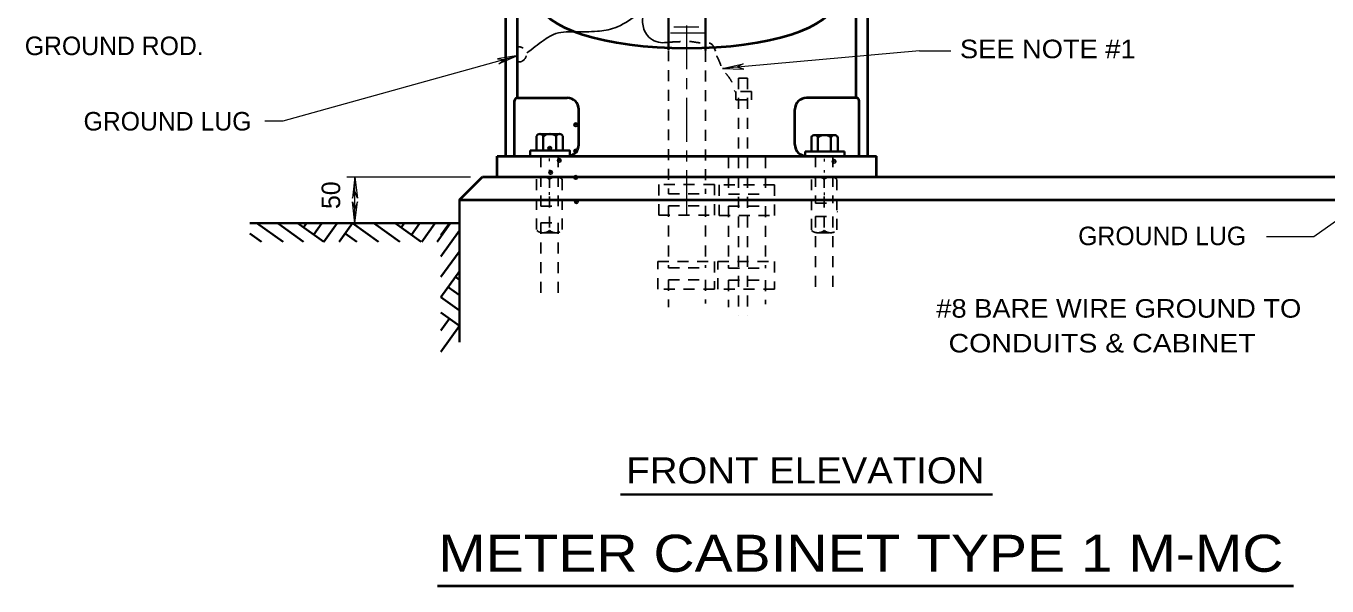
# Model space of a CAD drawing. Extents: x 312583 to 312854, y 144419 to 144597.
# Drawn here: x 312727.8 to 312781.2, y 144519.1 to 144542 of the extents above; entities that cross this region are included whole.
import ezdxf
from ezdxf.enums import TextEntityAlignment as Align

# ---------------------------------------------------------------- set-up
doc = ezdxf.new("R2010")
doc.units = 0
doc.header["$LTSCALE"] = 0.3
doc.header["$PDMODE"] = 32
doc.header["$PDSIZE"] = 0.15
for name, pattern in [('DOTTED', [1.5, 0.3, -1.2]), ('LONG_DASH_SHORT_DASH', [9.9, 6, -1.2, 1.5, -1.2]), ('SHORT_DASHED', [2.7, 1.5, -1.2])]:
    doc.linetypes.add(name, pattern=pattern)
doc.layers.add('1', color=7, linetype='Continuous', lineweight=25)
doc.layers.add('2', color=7, linetype='Continuous', lineweight=13)

msp = doc.modelspace()

# ---------------------------------------------------------------- linework, layer by layer
at = {"layer": '1', "lineweight": 40}
for p, q in [((312747.5013, 144536.686), (312747.5013, 144574.176)), ((312747.9843, 144539.078), (312747.9843, 144574.0686)), ((312761.8763, 144539.078), (312761.8763, 144547.0206)), ((312762.3593, 144536.686), (312762.3593, 144547.0206)), ((312747.8616, 144536.686), (312747.8616, 144538.963)), ((312747.9843, 144539.078), (312750.0159, 144539.078)), ((312761.8763, 144539.078), (312759.8369, 144539.078)), ((312761.9989, 144536.686), (312761.9989, 144538.963)), ((312750.4989, 144537.1613), (312750.4989, 144538.6026)), ((312759.3616, 144537.1613), (312759.3616, 144538.6026)), ((312747.1409, 144536.686), (312762.7119, 144536.686)), ((312747.1409, 144535.8426), (312747.1409, 144536.686)), ((312762.7119, 144535.8426), (312762.7119, 144536.686)), ((312745.6076, 144534.8996), (312746.5429, 144535.835)), ((312746.5429, 144535.835), (312818.4946, 144535.835)), ((312747.1409, 144535.8426), (312762.7119, 144535.8426)), ((312749.0346, 144535.835), (312749.5559, 144535.835)), ((312760.3046, 144535.835), (312760.8259, 144535.835)), ((312745.6076, 144534.8996), (312811.4873, 144534.8996)), ((312779.1799, 144534.8996), (312810.7283, 144534.8996))]:
    msp.add_line(p, q, dxfattribs=at)
at = {"layer": '1', "linetype": 'LONG_DASH_SHORT_DASH', "lineweight": 13}
msp.add_line((312754.9303, 144534.3093), (312754.9303, 144546.2156), dxfattribs=at)
at = {"layer": '1', "lineweight": 35}
for p, q in [((312754.1713, 144542.758), (312754.1713, 144541.0406)), ((312755.6893, 144542.758), (312755.6893, 144541.0176)), ((312748.7663, 144537.5063), (312748.7663, 144536.916)), ((312748.8966, 144537.5906), (312749.7016, 144537.5906)), ((312749.0346, 144537.5063), (312749.0346, 144536.916)), ((312749.5713, 144537.5063), (312749.5713, 144536.916)), ((312749.8396, 144537.5063), (312749.8396, 144536.916)), ((312760.0363, 144537.468), (312760.0363, 144536.8776)), ((312760.1743, 144537.5523), (312760.9793, 144537.5523)), ((312760.3046, 144537.468), (312760.3046, 144536.8776)), ((312760.8413, 144537.468), (312760.8413, 144536.8776)), ((312761.1173, 144537.468), (312761.1173, 144536.8776)), ((312748.4979, 144536.916), (312748.4979, 144536.686)), ((312748.7663, 144536.916), (312749.8396, 144536.916)), ((312759.7756, 144536.87), (312759.7756, 144536.686)), ((312759.7756, 144536.87), (312761.4009, 144536.87)), ((312760.0363, 144536.8776), (312761.1173, 144536.8776)), ((312761.4009, 144536.686), (312761.4009, 144536.87)), ((312745.6076, 144534.8996), (312745.6076, 144529.0576)), ((312736.9979, 144533.9413), (312745.6076, 144533.9413)), ((312738.3626, 144533.1746), (312737.2893, 144533.9413)), ((312739.2059, 144533.1746), (312738.1633, 144533.9183)), ((312740.0339, 144533.1746), (312738.9453, 144533.949)), ((312739.3209, 144533.9413), (312739.1983, 144533.765)), ((312739.9496, 144533.9413), (312739.6199, 144533.4736)), ((312740.5783, 144533.9413), (312740.0339, 144533.1746)), ((312741.2069, 144533.9413), (312740.6626, 144533.1746)), ((312742.2726, 144533.1746), (312741.2069, 144533.9413)), ((312743.1543, 144533.1746), (312742.0809, 144533.9413)), ((312744.0359, 144533.1746), (312742.9626, 144533.9413)), ((312743.3383, 144533.926), (312743.2156, 144533.7573)), ((312743.9669, 144533.926), (312743.6373, 144533.4583)), ((312744.5956, 144533.926), (312744.0513, 144533.167)), ((312745.2243, 144533.926), (312744.6799, 144533.167)), ((312744.8409, 144533.4506), (312745.1859, 144533.9413)), ((312737.4809, 144533.1746), (312736.9979, 144533.5196)), ((312741.3909, 144533.1746), (312740.9079, 144533.5196)), ((312744.8409, 144532.5766), (312745.6076, 144533.6423)), ((312744.8409, 144531.7333), (312745.5846, 144532.7683)), ((312744.8409, 144530.8976), (312745.6153, 144531.9863)), ((312745.6076, 144530.982), (312745.1399, 144531.3116)), ((312745.6076, 144531.6106), (312745.4313, 144531.7333)), ((312745.6076, 144530.3533), (312744.8409, 144530.8976)), ((312745.6076, 144529.7246), (312744.8409, 144530.269)), ((312744.8409, 144529.5406), (312745.1859, 144530.0236)), ((312744.8409, 144528.659), (312745.6076, 144529.7246))]:
    msp.add_line(p, q, dxfattribs=at)
at = {"layer": '1', "linetype": 'SHORT_DASHED'}
for p, q in [((312754.1713, 144541.0253), (312754.1713, 144535.1373)), ((312755.6893, 144541.01), (312755.6893, 144535.1373)), ((312757.0463, 144539.883), (312757.0463, 144530.1616)), ((312757.0463, 144539.883), (312757.4219, 144539.883)), ((312757.4219, 144539.883), (312757.4219, 144530.1616)), ((312748.9349, 144536.686), (312748.9349, 144534.639)), ((312749.6479, 144536.686), (312749.6479, 144534.639)), ((312756.6399, 144536.6476), (312756.6399, 144535.1296)), ((312758.1579, 144536.6476), (312758.1579, 144535.1296)), ((312760.2049, 144536.686), (312760.2049, 144534.754)), ((312760.9179, 144536.686), (312760.9179, 144534.754)), ((312748.7663, 144535.743), (312748.7663, 144533.6423)), ((312748.9349, 144535.835), (312749.6479, 144535.835)), ((312749.2953, 144535.835), (312749.2953, 144533.5426)), ((312749.8166, 144535.743), (312749.8166, 144533.6423)), ((312760.0363, 144535.7353), (312760.0363, 144533.6423)), ((312760.2049, 144535.835), (312760.9179, 144535.835)), ((312760.5653, 144535.835), (312760.5653, 144533.5426)), ((312761.0866, 144535.7353), (312761.0866, 144533.6423)), ((312754.1713, 144535.1373), (312755.6893, 144535.1373)), ((312756.6399, 144535.1296), (312758.1579, 144535.1296)), ((312748.9349, 144534.639), (312749.6479, 144534.639)), ((312754.1713, 144534.6466), (312755.6893, 144534.6466)), ((312754.1713, 144534.6466), (312754.1713, 144532.109)), ((312755.6893, 144534.6466), (312755.6893, 144532.109)), ((312756.6399, 144534.639), (312758.1579, 144534.639)), ((312756.6399, 144534.639), (312756.6399, 144532.0936)), ((312758.1579, 144534.639), (312758.1579, 144532.0936)), ((312760.2049, 144534.754), (312760.9179, 144534.754)), ((312748.9349, 144533.9566), (312749.6479, 144533.9566)), ((312748.9349, 144533.9566), (312748.9349, 144530.982)), ((312749.6479, 144533.9566), (312749.6479, 144530.982)), ((312760.2049, 144534.2096), (312760.9179, 144534.2096)), ((312760.2049, 144534.2096), (312760.2049, 144530.982)), ((312760.9179, 144534.2096), (312760.9179, 144530.982)), ((312749.0346, 144533.5426), (312749.5559, 144533.5426)), ((312760.3046, 144533.5426), (312760.8259, 144533.5426)), ((312754.1713, 144532.109), (312755.6893, 144532.109)), ((312756.6399, 144532.0936), (312758.1579, 144532.0936)), ((312754.1713, 144531.6183), (312755.6893, 144531.6183)), ((312754.1713, 144531.6183), (312754.1713, 144530.499)), ((312755.6893, 144531.6183), (312755.6893, 144530.637)), ((312756.6399, 144531.603), (312758.1579, 144531.603)), ((312756.6399, 144531.603), (312756.6399, 144530.4913)), ((312758.1579, 144531.603), (312758.1579, 144530.6216))]:
    msp.add_line(p, q, dxfattribs=at)
at = {"layer": '1', "linetype": 'DOTTED', "lineweight": 13}
for p, q in [((312749.2953, 144535.1066), (312749.2953, 144536.7473)), ((312760.5806, 144535.0913), (312760.5806, 144536.7626))]:
    msp.add_line(p, q, dxfattribs=at)
at = {"layer": '1', "lineweight": 13}
msp.add_line((312761.0866, 144534.4166), (312761.1096, 144534.409), dxfattribs=at)
at = {"layer": '1', "linetype": 'SHORT_DASHED'}
for points in [[(312756.9313, 144539.331), (312756.9313, 144538.9936), (312757.5829, 144538.9936), (312757.5829, 144539.331)], [(312753.7803, 144534.271), (312756.0573, 144534.271), (312756.0573, 144535.5206), (312753.7803, 144535.5206)], [(312756.2489, 144534.2556), (312758.5183, 144534.2556), (312758.5183, 144535.5053), (312756.2489, 144535.5053)], [(312753.7343, 144531.235), (312753.7343, 144532.3696), (312756.0573, 144532.3696), (312756.0573, 144531.235)], [(312756.2029, 144531.2273), (312756.2029, 144532.362), (312758.5183, 144532.362), (312758.5183, 144531.2273)]]:
    msp.add_lwpolyline(points, close=True, dxfattribs=at)
at = {"layer": '1', "lineweight": 35}
for points in [[(312748.9349, 144537.5906), (312749.2339, 144537.5906), (312749.1803, 144537.583), (312749.1496, 144537.5753), (312749.0959, 144537.5523), (312749.0346, 144537.514), (312749.0193, 144537.5446), (312748.9886, 144537.5676), (312748.9426, 144537.5906), (312749.2109, 144537.5906), (312749.1343, 144537.5753), (312749.0806, 144537.5523), (312749.0423, 144537.5216), (312748.9963, 144537.5676), (312748.9656, 144537.583), (312749.1803, 144537.5906), (312749.1036, 144537.5676), (312749.0423, 144537.5293), (312748.9809, 144537.583), (312749.1496, 144537.583), (312749.0346, 144537.537), (312748.9886, 144537.5753), (312749.1343, 144537.583), (312749.0346, 144537.5446), (312749.0039, 144537.5753), (312749.1113, 144537.5753), (312749.0346, 144537.5523), (312749.0116, 144537.5676), (312749.0806, 144537.5753), (312749.0423, 144537.5523), (312749.0269, 144537.5676), (312749.0576, 144537.5676), (312749.0346, 144537.56)], [(312749.6709, 144537.5906), (312749.3719, 144537.5906), (312749.4256, 144537.583), (312749.4563, 144537.5753), (312749.5099, 144537.5523), (312749.5713, 144537.514), (312749.5866, 144537.5446), (312749.6173, 144537.5676), (312749.6556, 144537.5906), (312749.3949, 144537.5906), (312749.4716, 144537.5753), (312749.5253, 144537.5523), (312749.5636, 144537.5216), (312749.6096, 144537.5676), (312749.6403, 144537.583), (312749.4256, 144537.5906), (312749.5023, 144537.5676), (312749.5636, 144537.5293), (312749.6249, 144537.583), (312749.4486, 144537.583), (312749.5713, 144537.537), (312749.6173, 144537.5753), (312749.4716, 144537.583), (312749.5713, 144537.5446), (312749.6019, 144537.5753), (312749.4946, 144537.5753), (312749.5713, 144537.5523), (312749.5943, 144537.5676), (312749.5253, 144537.5753), (312749.5636, 144537.5523), (312749.5789, 144537.5676), (312749.5483, 144537.5676), (312749.5636, 144537.56)], [(312760.2049, 144537.5523), (312760.5116, 144537.5523), (312760.4579, 144537.537), (312760.4196, 144537.5293), (312760.3659, 144537.5063), (312760.3123, 144537.468), (312760.2893, 144537.5063), (312760.2663, 144537.5216), (312760.2203, 144537.5446), (312760.4809, 144537.5446), (312760.4119, 144537.5293), (312760.3506, 144537.5063), (312760.3123, 144537.4833), (312760.2663, 144537.5216), (312760.2356, 144537.5446), (312760.4503, 144537.5446), (312760.3736, 144537.5216), (312760.3123, 144537.4833), (312760.2509, 144537.537), (312760.4273, 144537.5446), (312760.3123, 144537.491), (312760.2663, 144537.537), (312760.4043, 144537.537), (312760.3046, 144537.4986), (312760.2739, 144537.5293), (312760.3889, 144537.537), (312760.3123, 144537.5063), (312760.2893, 144537.5293), (312760.3583, 144537.5293), (312760.3123, 144537.514), (312760.3046, 144537.5293), (312760.3353, 144537.5216), (312760.3123, 144537.5216)], [(312760.9486, 144537.5523), (312760.6419, 144537.5523), (312760.6956, 144537.537), (312760.7263, 144537.5293), (312760.7876, 144537.5063), (312760.8413, 144537.468), (312760.8643, 144537.5063), (312760.8873, 144537.5216), (312760.9333, 144537.5446), (312760.6726, 144537.5446), (312760.7416, 144537.5293), (312760.7953, 144537.5063), (312760.8413, 144537.4833), (312760.8873, 144537.5216), (312760.9103, 144537.5446), (312760.7033, 144537.5446), (312760.7723, 144537.5216), (312760.8413, 144537.4833), (312760.9026, 144537.537), (312760.7263, 144537.5446), (312760.8413, 144537.491), (312760.8873, 144537.537), (312760.7416, 144537.537), (312760.8489, 144537.4986), (312760.8796, 144537.5293), (312760.7646, 144537.537), (312760.8413, 144537.5063), (312760.8643, 144537.5293), (312760.7953, 144537.5293), (312760.8413, 144537.514), (312760.8489, 144537.5293), (312760.8183, 144537.5216), (312760.8413, 144537.5216)], [(312748.4979, 144536.916), (312750.1309, 144536.916), (312750.1309, 144536.7013)]]:
    msp.add_lwpolyline(points, dxfattribs=at)
at = {"layer": '1', "linetype": 'SHORT_DASHED'}
for points in [[(312749.1036, 144535.8273), (312749.4869, 144535.835), (312749.4486, 144535.8196), (312749.4026, 144535.812), (312749.3566, 144535.789), (312749.3336, 144535.7736), (312749.2953, 144535.7506), (312749.2953, 144535.743), (312749.2186, 144535.7966), (312749.1573, 144535.8196), (312749.1189, 144535.8273), (312749.4639, 144535.8273), (312749.4333, 144535.8273), (312749.4026, 144535.8196), (312749.3643, 144535.8043), (312749.3183, 144535.7813), (312749.3029, 144535.766), (312749.2953, 144535.7506), (312749.2263, 144535.7966), (312749.1573, 144535.8273), (312749.4103, 144535.8273), (312749.3489, 144535.8043), (312749.2953, 144535.766), (312749.1803, 144535.8196), (312749.3873, 144535.8196), (312749.2953, 144535.766), (312749.2033, 144535.812), (312749.3643, 144535.8196), (312749.2953, 144535.7813), (312749.2416, 144535.812), (312749.3413, 144535.812), (312749.2953, 144535.7966), (312749.2339, 144535.8043), (312749.2723, 144535.7813), (312749.2799, 144535.8043), (312749.2876, 144535.7736), (312749.3106, 144535.7966), (312749.3259, 144535.8043), (312749.3489, 144535.8043)], [(312760.3736, 144535.8273), (312760.7569, 144535.8273), (312760.7186, 144535.8196), (312760.6726, 144535.812), (312760.6266, 144535.789), (312760.6036, 144535.7736), (312760.5653, 144535.7506), (312760.5653, 144535.743), (312760.4886, 144535.7966), (312760.4273, 144535.8196), (312760.3889, 144535.8273), (312760.7339, 144535.8273), (312760.7033, 144535.8273), (312760.6726, 144535.8196), (312760.6343, 144535.8043), (312760.5883, 144535.7813), (312760.5729, 144535.766), (312760.5653, 144535.7506), (312760.4963, 144535.7966), (312760.4273, 144535.8196), (312760.6803, 144535.8273), (312760.6189, 144535.8043), (312760.5653, 144535.766), (312760.4503, 144535.8196), (312760.6573, 144535.8196), (312760.5653, 144535.7583), (312760.4733, 144535.812), (312760.6343, 144535.8196), (312760.5653, 144535.7813), (312760.5116, 144535.812), (312760.6113, 144535.812), (312760.5653, 144535.7966), (312760.5039, 144535.8043), (312760.5423, 144535.7813), (312760.5499, 144535.8043), (312760.5576, 144535.7736), (312760.5806, 144535.7966), (312760.5959, 144535.7966), (312760.6189, 144535.8043)], [(312749.1036, 144533.5503), (312749.4869, 144533.5503), (312749.4486, 144533.558), (312749.4026, 144533.5656), (312749.3566, 144533.5886), (312749.3336, 144533.604), (312749.2953, 144533.627), (312749.2953, 144533.6346), (312749.2186, 144533.581), (312749.1573, 144533.558), (312749.1189, 144533.5503), (312749.4639, 144533.5503), (312749.4333, 144533.5503), (312749.4026, 144533.558), (312749.3643, 144533.5733), (312749.3183, 144533.5963), (312749.3029, 144533.6116), (312749.2953, 144533.627), (312749.2263, 144533.581), (312749.1573, 144533.558), (312749.4103, 144533.5503), (312749.3489, 144533.5733), (312749.2953, 144533.6116), (312749.1803, 144533.558), (312749.3873, 144533.558), (312749.2953, 144533.6193), (312749.2033, 144533.5656), (312749.3643, 144533.558), (312749.2953, 144533.5963), (312749.2416, 144533.5733), (312749.3413, 144533.5656), (312749.2953, 144533.581), (312749.2339, 144533.5733), (312749.2723, 144533.5963), (312749.2799, 144533.5733), (312749.2876, 144533.604), (312749.3106, 144533.581), (312749.3259, 144533.581), (312749.3489, 144533.5733)], [(312760.3736, 144533.5503), (312760.7569, 144533.5426), (312760.7186, 144533.558), (312760.6726, 144533.5656), (312760.6266, 144533.5886), (312760.6036, 144533.604), (312760.5653, 144533.627), (312760.5653, 144533.6346), (312760.4886, 144533.581), (312760.4273, 144533.558), (312760.3889, 144533.5503), (312760.7339, 144533.5503), (312760.7033, 144533.5503), (312760.6726, 144533.558), (312760.6343, 144533.5733), (312760.5883, 144533.5963), (312760.5729, 144533.6116), (312760.5653, 144533.627), (312760.4963, 144533.581), (312760.4273, 144533.5503), (312760.6803, 144533.5503), (312760.6189, 144533.5733), (312760.5653, 144533.6116), (312760.4503, 144533.558), (312760.6573, 144533.558), (312760.5653, 144533.6116), (312760.4733, 144533.5656), (312760.6343, 144533.558), (312760.5653, 144533.5963), (312760.5116, 144533.5656), (312760.6113, 144533.5656), (312760.5653, 144533.581), (312760.5039, 144533.5733), (312760.5423, 144533.5963), (312760.5499, 144533.5733), (312760.5576, 144533.604), (312760.5806, 144533.581), (312760.5959, 144533.5733), (312760.6189, 144533.5733)]]:
    msp.add_lwpolyline(points, dxfattribs=at)
at = {"layer": '1', "lineweight": 40}
for centre, radius, start, end in [((312747.9804, 144538.9601), 0.1198, 90, 180), ((312750.0169, 144538.6007), 0.4792, 0, 90), ((312759.8398, 144538.6007), 0.4792, 90, 180), ((312761.8763, 144538.9601), 0.1198, 0, 90), ((312750.0169, 144537.1632), 0.4792, 270, 0), ((312759.8398, 144537.1632), 0.4792, 180, 270)]:
    msp.add_arc(centre, radius, start, end, dxfattribs=at)
at = {"layer": '1', "lineweight": 35}
for centre, radius, start, end in [((312748.899, 144537.446), 0.1489, 25.60064, 154.39936), ((312749.302, 144537.1261), 0.4689, 55.04559, 124.95441), ((312749.705, 144537.446), 0.1489, 25.60064, 154.39936), ((312760.1729, 144537.4029), 0.1489, 25.60064, 154.39936), ((312760.5758, 144537.0829), 0.4689, 55.04559, 124.95441), ((312760.9788, 144537.4029), 0.1489, 25.60064, 154.39936)]:
    msp.add_arc(centre, radius, start, end, dxfattribs=at)
at = {"layer": '1', "linetype": 'SHORT_DASHED'}
for centre, start, end in [((312749.0302, 144535.4268), 50.00693, 129.99306), ((312749.5545, 144535.4268), 50.00694, 129.99307), ((312760.3002, 144535.4259), 50.00693, 129.99306), ((312760.8245, 144535.4259), 50.00694, 129.99307), ((312749.0302, 144533.9529), 230.00694, 309.99307), ((312749.5545, 144533.9529), 230.00693, 309.99306), ((312760.3002, 144533.9519), 230.00694, 309.99307), ((312760.8245, 144533.9519), 230.00693, 309.99306)]:
    msp.add_arc(centre, 0.4079, start, end, dxfattribs=at)
at = {"layer": '1', "lineweight": 40}
msp.add_ellipse((312754.9288, 144543.033), major_axis=(6.0495, 0), ratio=0.316832, start_param=3.1415927, end_param=6.2831853, dxfattribs=at)
at = {"layer": '1'}
msp.add_spline([(312748.3676, 144540.918), (312749.0499, 144541.4316), (312749.4563, 144541.677), (312750.2996, 144541.7843), (312751.2579, 144541.8073), (312751.9709, 144541.9453), (312752.8219, 144542.436), (312753.2896, 144542.9036), (312753.4659, 144543.172), (312753.4046, 144543.057), (312753.1133, 144542.1676), (312753.3126, 144541.631), (312753.9336, 144541.3396), (312754.2249, 144541.3626)], degree=3, dxfattribs=at)
at = {"layer": '1', "linetype": 'SHORT_DASHED'}
for points in [[(312754.2249, 144541.3626), (312754.7616, 144541.3856), (312755.0989, 144541.3856), (312755.4133, 144541.3396), (312755.9193, 144541.2936), (312756.1493, 144540.803)], [(312756.1493, 144540.803), (312756.3103, 144540.4426), (312756.3486, 144540.3353), (312756.4866, 144540.1283), (312756.6629, 144539.906), (312756.8009, 144539.6376), (312756.8393, 144539.4383), (312756.9313, 144539.308)]]:
    msp.add_spline(points, degree=3, dxfattribs=at)
at = {"layer": '1'}
for p in [(312750.3686, 144537.974), (312749.3029, 144537.008), (312749.6939, 144536.5096), (312750.3686, 144536.893), (312749.3413, 144536.019), (312760.9716, 144536.4713), (312750.3686, 144535.812), (312750.3993, 144534.823)]:
    msp.add_point(p, dxfattribs=at)
at = {"layer": '2'}
for p, q in [((312754.4013, 144541.9913), (312755.4209, 144541.9913)), ((312754.2633, 144541.746), (312755.6433, 144541.746)), ((312764.4753, 144541.0023), (312756.3869, 144540.2816)), ((312764.4753, 144541.0023), (312765.7556, 144541.0023)), ((312738.3639, 144538.132), (312748.0149, 144540.8106)), ((312748.0149, 144540.8106), (312747.1563, 144540.6803)), ((312747.1563, 144540.6803), (312747.4476, 144540.6496)), ((312748.0149, 144540.8106), (312747.2099, 144540.4733)), ((312747.2099, 144540.4733), (312747.4476, 144540.6496)), ((312756.3869, 144540.2816), (312757.2379, 144540.4656)), ((312757.2379, 144540.4656), (312756.9773, 144540.3353)), ((312757.2609, 144540.251), (312756.9773, 144540.3353)), ((312756.3869, 144540.2816), (312757.2609, 144540.251)), ((312737.6121, 144538.132), (312738.3639, 144538.132)), ((312780.6443, 144533.397), (312785.2979, 144536.663)), ((312740.9769, 144535.835), (312746.0599, 144535.835)), ((312741.3143, 144535.835), (312741.2069, 144534.9686)), ((312741.3143, 144533.9413), (312741.3143, 144535.835)), ((312741.3143, 144535.835), (312741.4216, 144534.9686)), ((312741.2069, 144534.9686), (312741.3143, 144535.2446)), ((312741.4216, 144534.9686), (312741.3143, 144535.2446)), ((312741.2069, 144534.8076), (312741.3143, 144534.5316)), ((312741.3143, 144533.9413), (312741.2069, 144534.8076)), ((312741.4216, 144534.8076), (312741.3143, 144534.5316)), ((312741.3143, 144533.9413), (312741.4216, 144534.8076)), ((312778.7046, 144533.397), (312780.6443, 144533.397))]:
    msp.add_line(p, q, dxfattribs=at)
at = {"layer": '2', "lineweight": 35}
msp.add_line((312752.2017, 144522.8095), (312767.4734, 144522.8095), dxfattribs=at)
at = {"layer": '2', "lineweight": 40}
msp.add_line((312744.6953, 144519.0606), (312779.8152, 144519.0606), dxfattribs=at)
at = {"layer": '2', "linetype": 'SHORT_DASHED', "lineweight": 25}
msp.add_arc((312748.036, 144540.8586), 0.3097, 264.63342, 94.61635, dxfattribs=at)

# ---------------------------------------------------------------- texts
at = {"layer": '2'}
for s, p in [('GROUND ROD.', (312727.7681, 144540.8291)), ('GROUND LUG', (312730.1795, 144537.7376)), ('GROUND LUG', (312770.9823, 144533.0356))]:
    msp.add_text(s, height=0.76, dxfattribs=at).set_placement(p)
for s, width, p in [('SEE NOTE #1', 1.1, (312766.1313, 144540.7023)), ('#8 BARE WIRE GROUND TO', 1.1, (312765.1627, 144530.0633)), ('CONDUITS & CABINET', 1.15, (312765.6644, 144528.6373))]:
    msp.add_text(s, height=0.76, dxfattribs=dict(at, width=width)).set_placement(p)
msp.add_text('50', height=0.76, rotation=90, dxfattribs=at).set_placement((312740.7064, 144534.5199))
for s, height, width, p in [('FRONT ELEVATION', 1.07, 1.1, (312759.7921, 144523.2639)), ('METER CABINET TYPE 1 M-MC', 1.52, 1.15, (312762.0653, 144519.6417))]:
    msp.add_text(s, height=height, dxfattribs=dict(at, width=width)).set_placement(p, align=Align.CENTER)

doc.saveas('drawing.dxf')
